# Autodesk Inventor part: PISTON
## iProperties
Shininess: 64.0
Length Units: 11269
Angle Units: 11279
Time Units: 11290
Mass Units: 11283
Length Display Precision: 3
Angle Display Precision: 2
Compacted: True
Part Number: PISTON
Document SubType Name: Modeling
Created: 2004-03
Designer: Daniel
Manufacturer: Standard
Standards Organization: Custom
Density: 0.0
Volumn: 0.0
Area: 0.0
PropertySet Name: Model Information
Control State: 0
Master: False
Checked Out: False
Author: Daniel
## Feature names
1. Extrusion1
2. Extrusion4
3. Extrusion5
4. Extrusion6
5. Fillet1
